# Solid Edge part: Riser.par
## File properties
Author: Dan
Template: metric part.par
Last saved by: Dan
Revision: 17
Application: Solid Edge
Density: 7833.000 kg/m^3
Accuracy: 0.990
Material: Steel
Face Style: Steel
Fill Style: ANSI32(Steel)
Virtual Style: Machined steel
Coef. of Thermal Exp: 1.3e-05
Thermal Conductivity: 32.0
Specific Heat: 481.0
Modulus of Elasticity: 199947953000.0
Poisson's Ratio: 0.29
Yield Stress: 262000766.0
Ultimate Stress: 358527364.0
Elongation: 0.0
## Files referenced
..\Moving Half.asm
C:\Drawing Files Other\Dave\Tente\HUP 125X36H45-TSA 02-07-2011\Wheel Mould\MH Clamping Plate.par
ZC:\Drawing Files Other\Dave\Tente\HUP 125X36H45-TSA 02-07-2011\Wheel Mould\Moving Half.asm
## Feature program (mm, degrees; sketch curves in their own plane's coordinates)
sketch for "unnamed Protrusion 1" plane through (0, 0, 0) normal (0, 0, 1) x-axis (1, 0, 0)
extrude "unnamed Protrusion 1" add finite 86 along -normal
sketch for "Hole_9" plane through (0, 0, 0) normal (0, 0, 1) x-axis (-1, 0, 0)
  hole centre (0, 116) bore radius 8.25
hole "Hole_9" diameter 16.5 through  VBottomAngle = 118 deg
sketch for "unnamed Hole 1" plane through (0, 0, 0) normal (0, 0, 1) x-axis (-1, 0, 0)
hole "unnamed Hole 1" through
pattern "unnamed Pattern 1" of "Hole_9", "unnamed Hole 1"
sketch for "unnamed Cutout 1" #1 plane through (0, 0, -86) normal (0, 0, -1) x-axis (0, 1, 0)
sketch for "unnamed Cutout 1" #2 plane through (0, 0, -86) normal (0, 0, -1) x-axis (0, 1, 0)
sketch for "unnamed Cutout 1" #3 plane through (0, 0, -86) normal (0, 0, -1) x-axis (0, 1, 0)
  circle centre (0, 0) radius 6.25
extrude "unnamed Cutout 1" cut through along -normal
delete holes assoc c "unnamed DeleteHolesAssocC 1"
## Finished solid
Body 1: solid body, 9 faces, 18 edges, 8 vertices.
  Faces by surface: plane 6, cylinder 3
  Edges by curve: line 12, circle 6
Bounding box of the edges (mm): 56.000 x 396.000 x 86.000, from (-28, -198, -86) to (28, 198, 0).
Cylindrical faces by radius (mm): R6.25 x3
Planar faces by outward normal: +x 1, +y 1, +z 1, -x 1, -y 1, -z 1
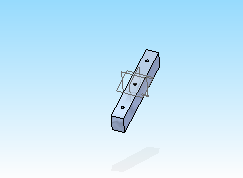
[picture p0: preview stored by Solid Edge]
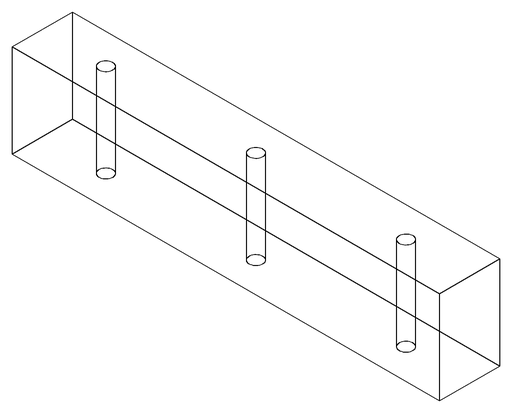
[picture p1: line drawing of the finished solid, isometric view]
